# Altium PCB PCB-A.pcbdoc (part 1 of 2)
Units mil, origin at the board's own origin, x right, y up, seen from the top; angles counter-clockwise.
Board outline 4955 x 3850 mil, 4 copper layers (Top Layer, Inner1, Inner2, Bottom Layer); 128 components, 159 nets, 685 pads, 359 vias.
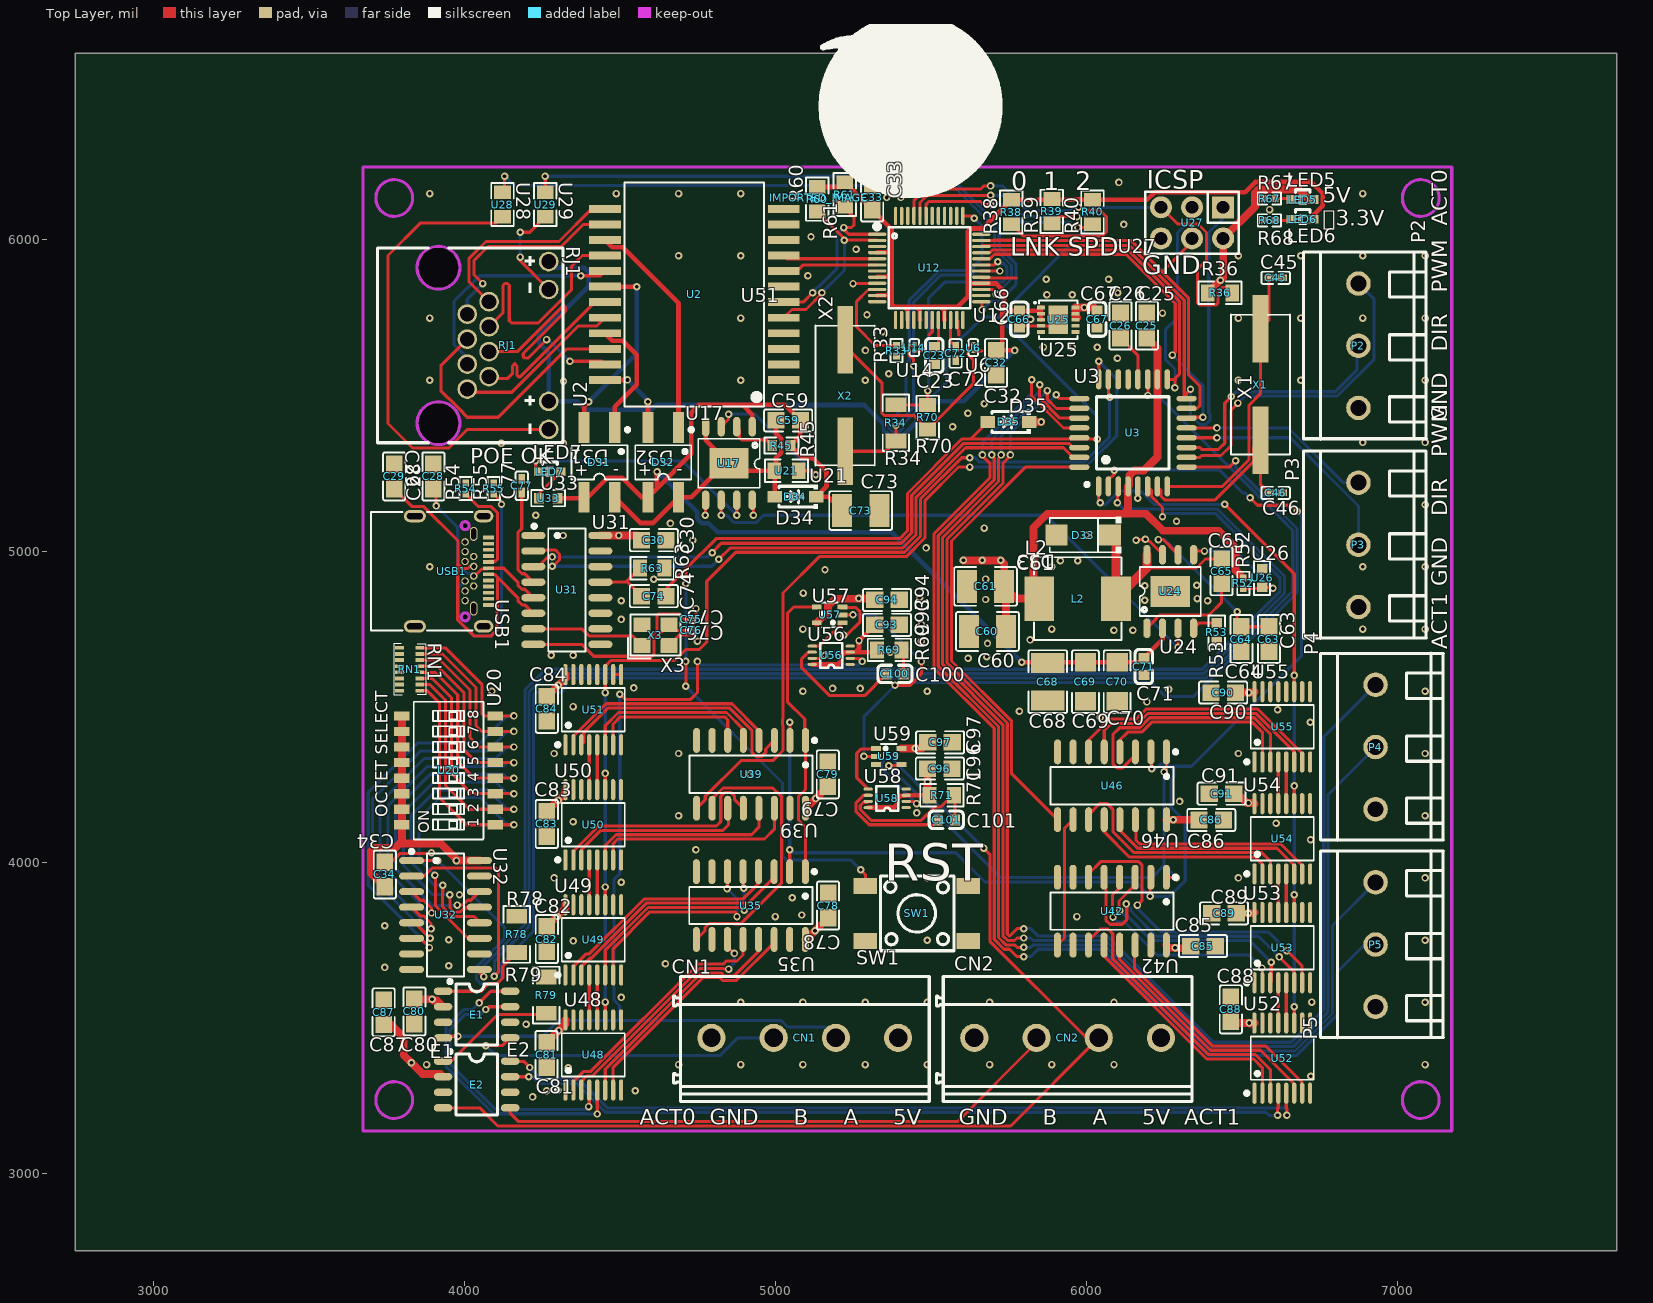
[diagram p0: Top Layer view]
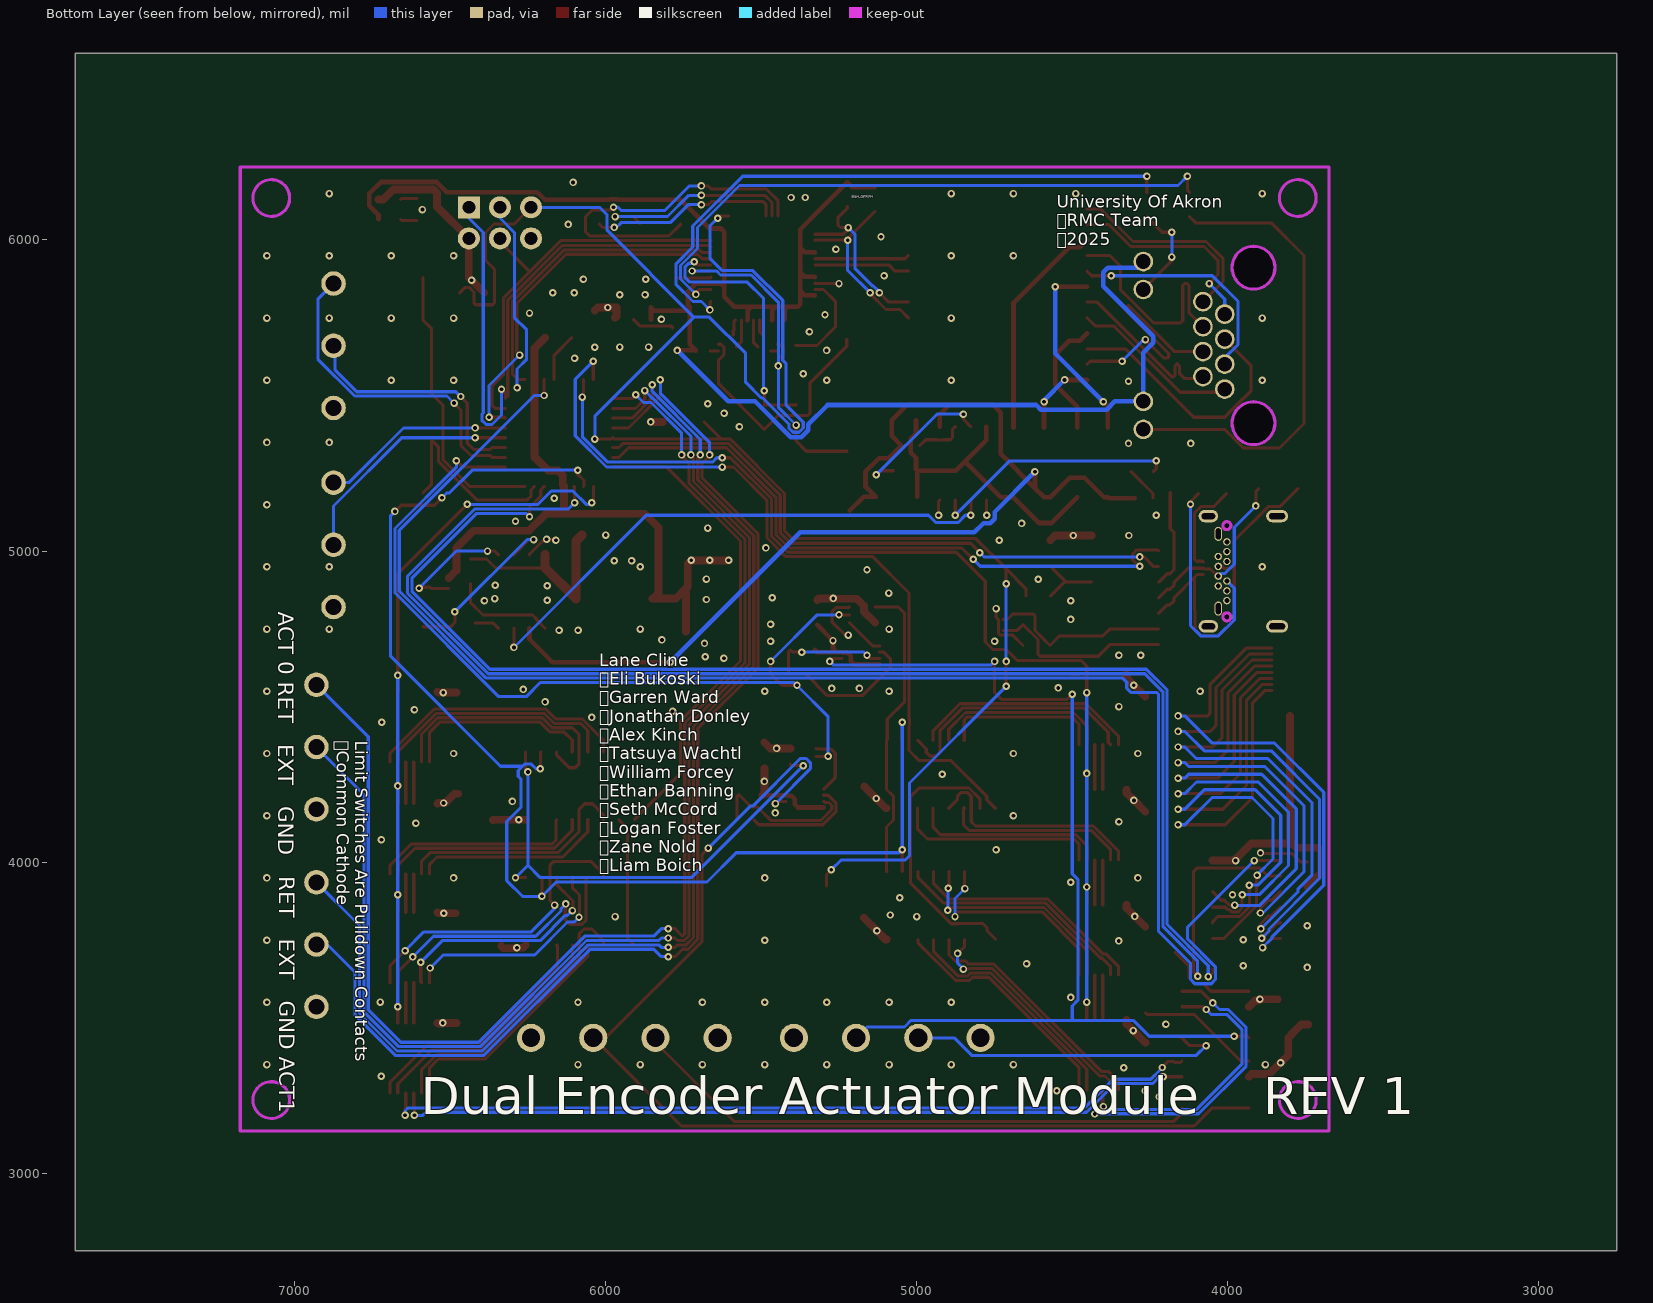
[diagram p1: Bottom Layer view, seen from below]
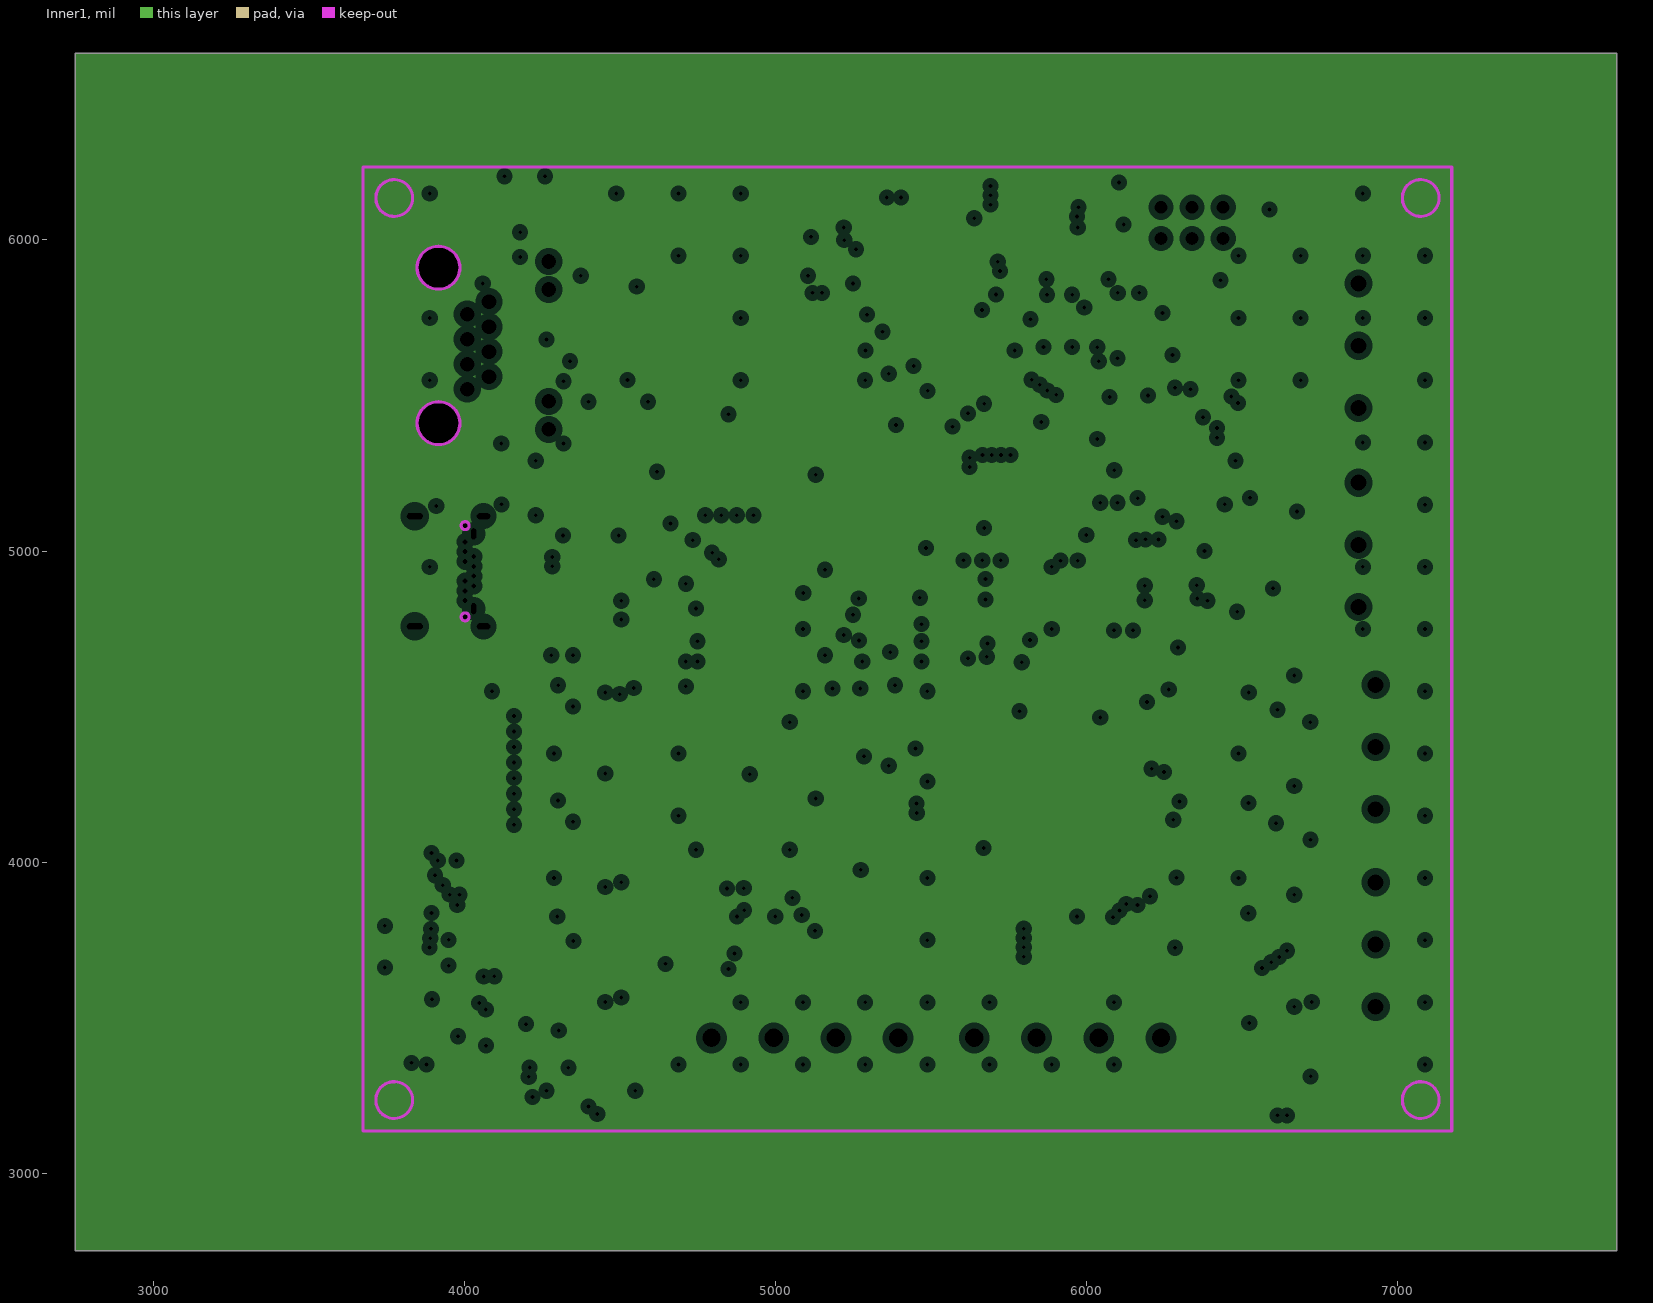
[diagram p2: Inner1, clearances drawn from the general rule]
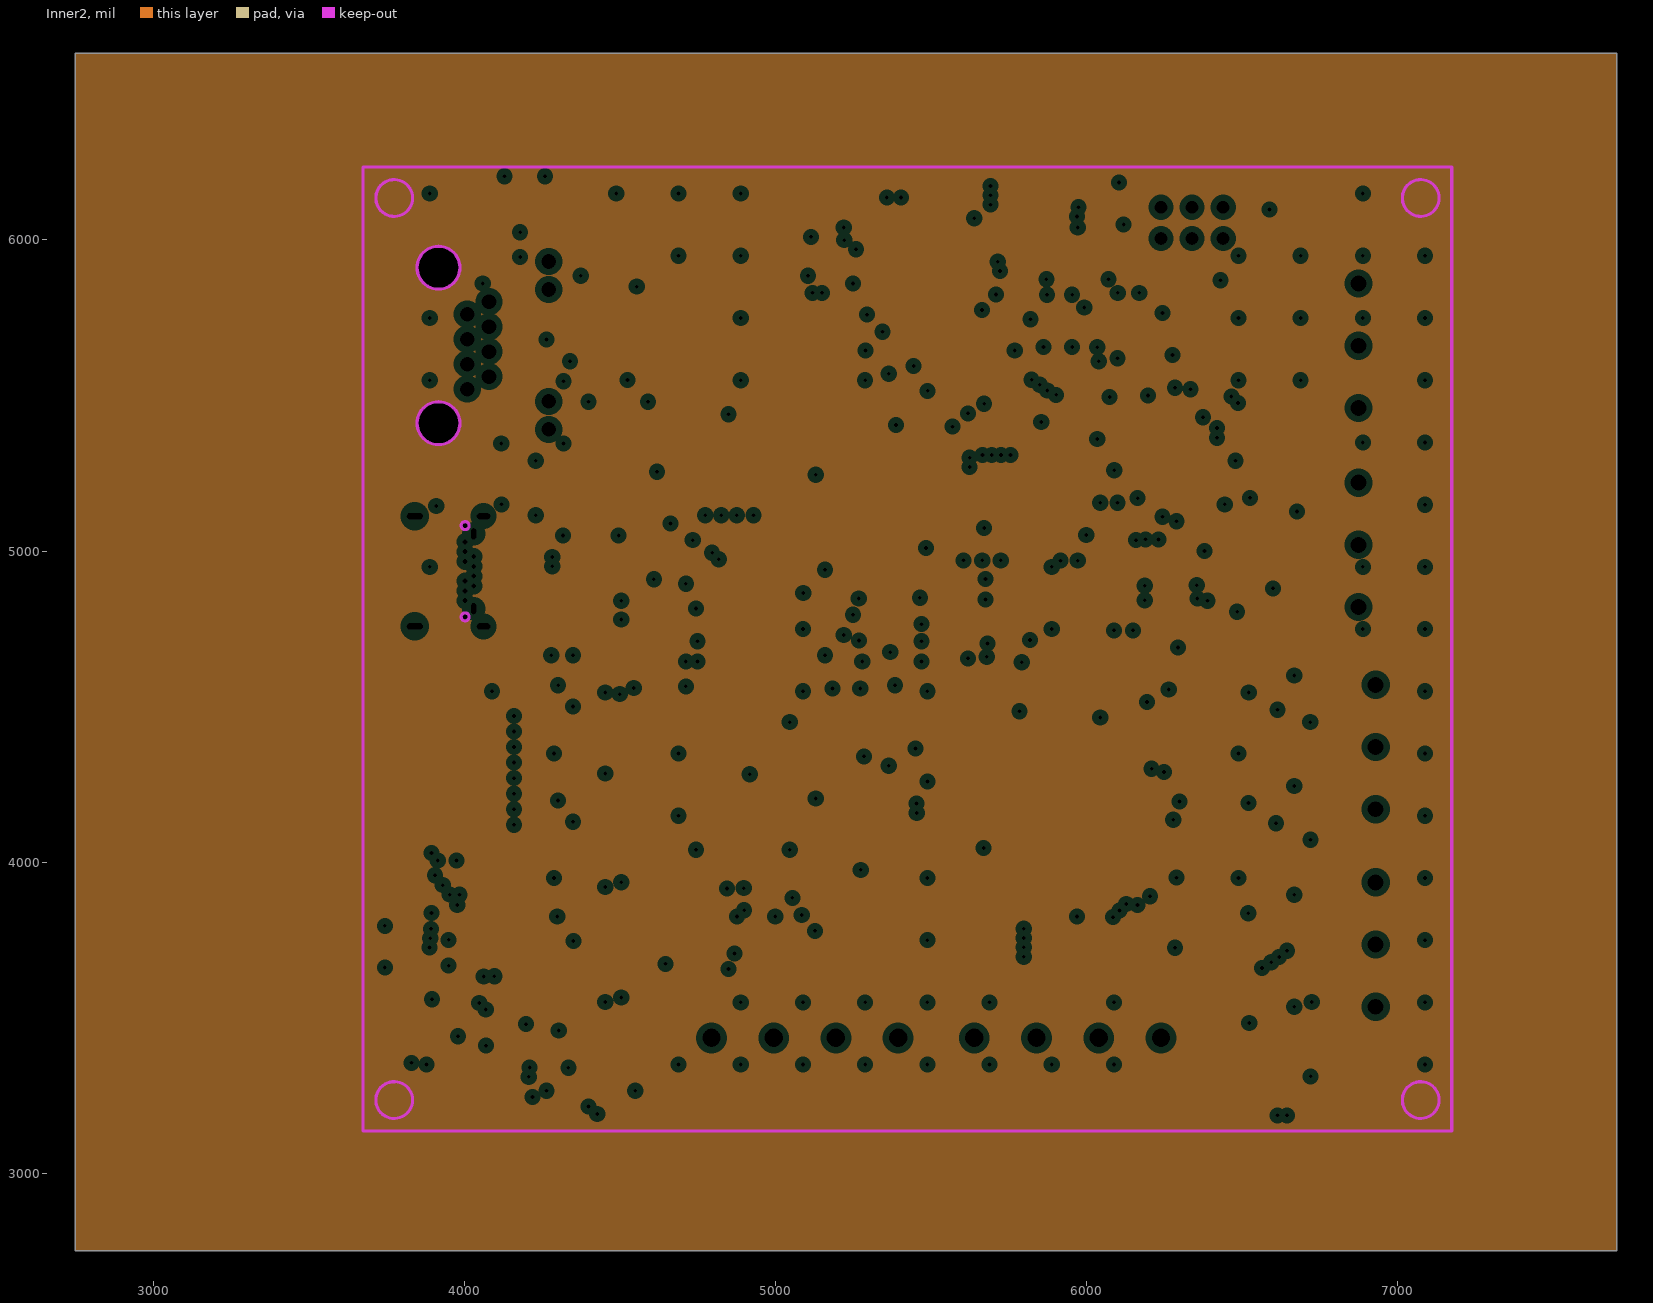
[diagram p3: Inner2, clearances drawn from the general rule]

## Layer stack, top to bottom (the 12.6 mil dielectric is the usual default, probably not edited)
Top Layer: signal copper (thickness not stored)
Dielectric: dielectric 12.6, FR-4, Dk 4.8
Inner1: plane copper (thickness not stored)
Dielectric: dielectric 12.6, FR-4, Dk 4.8
Inner2: plane copper (thickness not stored)
Dielectric: dielectric 12.6, FR-4, Dk 4.8
Bottom Layer: signal copper (thickness not stored)

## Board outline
7705,2750 2750,2750 2750,6600 7705,6600

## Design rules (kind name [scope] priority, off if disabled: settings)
BoardOutlineClearance copperThickness1oz [All] p0: genericclearance=10 ignorepadtopadclearanceinfootprint=FALSE except(0: Arc-SplitContinuation Track-SplitContinuation SMDPad-SplitContinuation THPad-SplitContinuation Via-SplitContinuation Fill-SplitContinuation Poly-SplitContinuation Region-SplitContinuation Text-SplitContinuation; 6: Track-CutoutEdge SMDPad-CutoutEdge THPad-CutoutEdge Via-CutoutEdge Region-CutoutEdge; 11.8: Track-OutlineEdge SMDPad-OutlineEdge THPad-OutlineEdge Via-OutlineEdge Fill-OutlineEdge Region-OutlineEdge Poly-OutlineEdge Text-OutlineEdge Fill-CutoutEdge)
BoardOutlineClearance copperThickness2oz [All] p0: genericclearance=10 ignorepadtopadclearanceinfootprint=FALSE except(0: Arc-SplitContinuation Track-SplitContinuation SMDPad-SplitContinuation THPad-SplitContinuation Via-SplitContinuation Fill-SplitContinuation Poly-SplitContinuation Region-SplitContinuation Text-SplitContinuation; 6: Track-CutoutEdge SMDPad-CutoutEdge THPad-CutoutEdge Via-CutoutEdge Region-CutoutEdge; 11.8: Track-OutlineEdge SMDPad-OutlineEdge THPad-OutlineEdge Via-OutlineEdge Fill-OutlineEdge Region-OutlineEdge Poly-OutlineEdge Text-OutlineEdge Fill-CutoutEdge)
Clearance copperThickness1oz [(InNet('D8') OR InNet('A0') OR InNet('A1') OR InNet('A2') OR InNet('A3') OR InNet('A4') OR InNet('A5') OR InNet('A6') OR InNet('A7') OR InNet('D9') OR InNet('W5500INT') OR InNet('+5V') OR InNet('ETH1A') OR InNet('ETH1B') OR InNet('ETH2A') OR InNet('ETH2B') OR InNet('ETH3A') OR InNet('ETH3B') OR InNet('ETH4A') OR InNet('ETH4B') OR InNet('+33V') OR InNet('RST') OR InNet('DP1') OR InNet('DN1') OR InNet('MISO') OR InNet('SCLK') OR InNet('MOSI') OR InNet('IP5') OR InNet('IP6') OR InNet('IP3') OR InNet('IP4') OR InNet('IP0') OR InNet('IP2') OR InNet('IP1') OR InNet('IP7') OR InNet('D1') OR InNet('D0') OR InNet('W5500CS') OR InNet('OCTR') OR InNet('OCTCLK') OR InNet('AGND') OR InNet('LINKLED') OR InNet('RJ4B') OR InNet('RJ4A') OR InNet('RJ3B') OR InNet('RJ1B') OR InNet('RJ1A') OR InNet('RJ3A') OR InNet('RJ2B') OR InNet('RJ2A') OR InNet('XTAL2') OR InNet('XTAL1') OR InNet('POE+') OR InNet('POE-') OR InNet('CDB') OR InNet('$7N5366') OR InNet('$12N45694') OR InNet('$7N5367') OR InNet('$6N13268') OR InNet('$12N45692') OR InNet('$12N45698') OR InNet('$12N45693') OR InNet('$12N45721') OR InNet('$12N45670') OR InNet('$12N45671') OR InNet('$12N45683') OR InNet('$7N5372') OR InNet('$7N5371') OR InNet('$7N5381') OR InNet('$7N5382') OR InNet('$7N5383') OR InNet('$12N45677') OR InNet('$7N5378') OR InNet('$12N45691') OR InNet('$12N45682') OR InNet('$12N45681') OR InNet('$7N5370') OR InNet('ACTLED') OR InNet('$12N45711') OR InNet('$12N45676') OR InNet('$6N13271') OR InNet('$6N13316') OR InNet('$6N13331') OR InNet('$6N13333') OR InNet('$6N13334') OR InNet('$6N13298') OR InNet('$5N10232') OR InNet('$14N15270') OR InNet('$12N45719') OR InNet('$12N45720') OR InNet('$12N45712') OR InNet('ACT0D1') OR InNet('ACT0D0') OR InNet('$5N10278') OR InNet('$5N10284') OR InNet('ACT0D2') OR InNet('ACT0D3') OR InNet('$5N10573') OR InNet('$5N10565') OR InNet('ACT0D4') OR InNet('ACT0D5') OR InNet('ACT0D6') OR InNet('ACT0D7') OR InNet('$5N9655') OR InNet('ACT0D8') OR InNet('ACT0D9') OR InNet('ACT0D10') OR InNet('ACT0D11') OR InNet('$5N11107') OR InNet('$5N11099') OR InNet('ACT0D12') OR InNet('ACT0D13') OR InNet('ACT0D14') OR InNet('ACT0D15') OR InNet('ACT1D1') OR InNet('ACT1D0') OR InNet('$14N15281') OR InNet('$14N15285') OR InNet('$14N15320') OR InNet('$14N15314') OR InNet('ACT1D4') OR InNet('ACT1D5') OR InNet('ACT1D6') OR InNet('ACT1D7') OR InNet('ACT1D3') OR InNet('ACT1D2') OR InNet('$14N15222') OR InNet('$14N15352') OR InNet('$14N15358') OR InNet('ACT1D8') OR InNet('ACT1D9') OR InNet('ACT1D10') OR InNet('ACT1D11') OR InNet('$14N15396') OR InNet('$14N15390') OR InNet('ACT1D12') OR InNet('ACT1D13') OR InNet('ACT1D14') OR InNet('ACT1D15') OR InNet('$5N14307') OR InNet('$5N14282') OR InNet('ACTCLK') OR InNet('ACTLD') OR InNet('ACT1CLR') OR InNet('ACT1RD') OR InNet('D6') OR InNet('D7') OR InNet('ACT0A') OR InNet('$5N17842') OR InNet('$5N17521') OR InNet('$5N17525') OR InNet('$5N17822') OR InNet('ACT1A') OR InNet('$14N18897') OR InNet('$14N18888') OR InNet('$14N18889') OR InNet('$14N18895') OR InNet('$5N20452') OR InNet('$14N20057'))] p1: gap=7 ignorepadtopadclearanceinfootprint=FALSE except(4: Track-Track; 6: Track-SMDPad SMDPad-SMDPad Track-THPad SMDPad-THPad THPad-THPad Track-Via SMDPad-Via THPad-Via Via-Via SMDPad-Fill THPad-Fill Via-Fill Fill-Fill Track-Region SMDPad-Region THPad-Region Via-Region Region-Region Track-Poly SMDPad-Poly THPad-Poly Via-Poly Fill-Poly Region-Poly Poly-Poly Track-Text SMDPad-Text THPad-Text Via-Text Fill-Text Region-Text Poly-Text Text-Text; 6.9: Track-Hole SMDPad-Hole THPad-Hole Via-Hole Fill-Hole Region-Hole Poly-Hole Text-Hole Sheet-Hole; 11.8: Track-Fill Fill-Region Track-Sheet SMDPad-Sheet THPad-Sheet Via-Sheet Fill-Sheet Region-Sheet Poly-Sheet Text-Sheet)
Clearance copperThickness2oz [All] p1: gap=7 ignorepadtopadclearanceinfootprint=FALSE except(6: Track-SMDPad SMDPad-SMDPad Track-THPad SMDPad-THPad THPad-THPad Track-Via SMDPad-Via THPad-Via Via-Via SMDPad-Fill THPad-Fill Via-Fill Fill-Fill Track-Region SMDPad-Region THPad-Region Via-Region Region-Region Track-Poly SMDPad-Poly THPad-Poly Via-Poly Fill-Poly Region-Poly Poly-Poly Track-Text SMDPad-Text THPad-Text Via-Text Fill-Text Region-Text Poly-Text Text-Text; 6.9: Track-Hole SMDPad-Hole THPad-Hole Via-Hole Fill-Hole Region-Hole Poly-Hole Text-Hole Sheet-Hole; 8: Track-Track; 11.8: Track-Fill Fill-Region Track-Sheet SMDPad-Sheet THPad-Sheet Via-Sheet Fill-Sheet Region-Sheet Poly-Sheet Text-Sheet)
DiffPairsRouting differentialPair [All] p1: maxuncoupledlength=10 minlimit=6 maxlimit=6 mostfreqgap=6 toplayer_minwidth=5 toplayer_prefwidth=10 toplayer_maxwidth=100 bottomlayer_minwidth=5 bottomlayer_prefwidth=10 bottomlayer_maxwidth=100
DiffPairsRouting differentialPair1 [All] p1: maxuncoupledlength=10 minlimit=6 maxlimit=6 mostfreqgap=6 toplayer_minwidth=5 toplayer_prefwidth=10 toplayer_maxwidth=100 bottomlayer_minwidth=5 bottomlayer_prefwidth=10 bottomlayer_maxwidth=100
PasteMaskExpansion pasteMaskExpansion [All] p1: expansion=0
PlaneConnect innerPlane [All] p1: planeconnectstyle=Relief reliefexpansion=20 reliefentries=4 reliefconductorwidth=10 reliefairgap=10
PolygonConnect copperRegion [All] p1: connectstyle=Relief reliefentries=4 reliefconductorwidth=10 polygonreliefangle="90 Angle" airgapwidth=10
RoutingVias viaSize [All] p1: viastyle="Through Hole" holewidth=12 minholewidth=11.8 maxholewidth=248 width=24 minwidth=19.7 maxwidth=393.7
SolderMaskExpansion solderMaskExpansion [All] p1: useseparateexpansions=TRUE expansion=2 expansionbottom=2
Width copperThickness1oz [All] p1: maxlimit=100 minlimit=5 preferedwidth=10
Width copperThickness2oz [All] p1: maxlimit=100 minlimit=8 preferedwidth=10
Width powa [All] p1: maxlimit=50 minlimit=10 preferedwidth=25
Width 3v [All] p1: maxlimit=100 minlimit=10 preferedwidth=15

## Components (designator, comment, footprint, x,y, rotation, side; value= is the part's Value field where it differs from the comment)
C23 "CL10A475KQ8NNNC" C0603 5511.34,5628.82 r90 top
C25 "0805B104K500NT" C0805 6195,5725 r90 top
C26 "0805B104K500NT" C0805 6110,5725 r270 top
C28 "CL21C470JBANNNC" C0805 3901.03,5240 r270 top
C29 "CL21C470JBANNNC" C0805 3775,5240 r270 top
C30 "0805B104K500NT" C0805 4609.79,5035 r0 top
C32 "0805B104K500NT" C0805 5710,5605 r270 top
C33 "0805B104K500NT" C0805 5311.55,6136.59 r90 top
C34 "0805B104K500NT" C0805 3744.79,3960.35 r270 top
C45 "CC0402JRNPO9BN120" C0402 6608.74,5878.41 r0 top
C46 "CC0402JRNPO9BN120" C0402 6608.74,5186.99 r180 top
C59 "0805B104K500NT" C0805 5041.57,5420 r180 top
C60 "CS3225X7R476K160NRL" C1210 5682.35,4741.37 r0 top
C61 "CS3225X7R476K160NRL" C1210 5676.27,4886.37 r0 top
C63 "0805F403M500NT" C0805 6587.35,4717.13 r90 top
C64 "0805F403M500NT" C0805 6498.57,4717.13 r90 top
C65 "0805B104K500NT" C0805 6435,4935 r270 top
C66 "CL10A225KO8NNNC" C0603 5785,5745.33 r90 top
C67 "CL10A225KO8NNNC" C0603 6035,5745.33 r90 top
C68 "FS32X106K101EGG" C1210 5876.04,4580.01 r90 top
C69 "CC1206KKX7R0BB225" C1206 5997.24,4580 r90 top
C70 "CC1206KKX7R0BB225" C1206 6099.31,4580 r90 top
C71 "CC0603KRX7R0BB104" C0603 6185.08,4628.63 r90 top
C72 "CC0402KRX7R9BB103" C0402 5579.8,5635.11 r90 top
C73 "FS32X106K101EGG" C1210 5274.74,5130.26 r180 top
C74 "0805B104K500NT" C0805 4609.79,4855 r180 top
C75 "GRM0225C1E220JA02L" C01005 4730,4780 r180 top
C76 "GRM0225C1E220JA02L" C01005 4730,4745 r180 top
C77 "CC0402JRNPO9BN120" C0402 4185,5209.89 r270 top
C78 "0805B104K500NT" C0805 5170,3860.37 r90 top
C79 "0805B104K500NT" C0805 5168.89,4282.28 r270 top
C80 "0805B104K500NT" C0805 3840,3520 r90 top
C81 "0805B104K500NT" C0805 4265,3380 r270 top
C82 "0805B104K500NT" C0805 4265.66,3752.53 r270 top
C83 "0805B104K500NT" C0805 4265.66,4122.73 r270 top
C84 "0805B104K500NT" C0805 4265.66,4492.93 r270 top
C85 "0805B104K500NT" C0805 6375,3730 r0 top
C86 "0805B104K500NT" C0805 6401.81,4135.37 r180 top
C87 "0805B104K500NT" C0805 3741.36,3517.27 r270 top
C88 "0805B104K500NT" C0805 6464.74,3526.65 r90 top
C89 "0805B104K500NT" C0805 6443.03,3835.37 r180 top
C90 "0805B104K500NT" C0805 6440,4545 r180 top
C91 "0805B104K500NT" C0805 6435,4220 r180 top
C93 "0805B104K500NT" C0805 5359.28,4762.74 r0 top
C94 "0805B104K500NT" C0805 5359.58,4842.74 r180 top
C96 "0805B104K500NT" C0805 5529.19,4300.66 r0 top
C97 "0805B104K500NT" C0805 5530,4385 r180 top
C100 "CC0603JRNPO9BN270" C0603 5385,4605 r0 top
C101 "CC0603JRNPO9BN270" C0603 5550,4135.8 r0 top
CN1 "DB128V-5.08-4P-GN-S" CONN-TH_4P-P5.08_DIBO_DB128V-5.08 5095,3435 r0 top
CN2 "DB128V-5.08-4P-GN-S" CONN-TH_4P-P5.08_DIBO_DB128V-5.08 5940,3435 r0 top
D31 "MB110S_C382811" MBS_L4.7-W4.0-P2.50-LS7.0-BL 4435,5285 r180 top
D32 "MB110S_C382811" MBS_L4.7-W4.0-P2.50-LS7.0-BL 4640,5285 r180 top
D33 "SS36_C727061" SMA_L4.4-W2.6-LS5.0-RD 5990,5051.37 r180 top
D34 "LMSZ5264BT1G" SOD-123_L2.7-W1.6-LS3.7-RD-1 5065,5175 r180 top
D35 "LMSZ5264BT1G" SOD-123_L2.7-W1.6-LS3.7-RD-1 5750,5415 r180 top
E1 "LS7183N-S" SOIC-8_L5.0-W4.0-P1.27-LS6.0-TL 4040,3510 r0 top
E2 "LS7183N-S" SOIC-8_L5.0-W4.0-P1.27-LS6.0-TL 4040,3285 r0 top
IMPORTED_IMAGE "IMPORTED_IMAGE" IMPORTED_IMAGE 5140,6135 r0 top
L2 "FXL0630-8R2-M" IND-SMD_L7.0-W6.6_FXL0630 5972.3,4847.13 r0 top
LED5 "TJ-S1706SW6TGLC7K-A5" LED-SMD_L1.7-W0.6-RD_GREEN 6695.14,6130.02 r0 top
LED6 "TJ-S1706SW6TGLC7K-A5" LED-SMD_L1.7-W0.6-RD_GREEN 6695.14,6066.15 r0 top
LED7 "TJ-S1706SW6TGLC7K-A5" LED-SMD_L1.7-W0.6-RD_GREEN 4275,5255 r0 top
P2 "WJ500V-5.08-3P" CONN-TH_3P-P5.00_WJ500V-5.08-3P 6875,5660 r90 top
P3 "WJ500V-5.08-3P" CONN-TH_3P-P5.00_WJ500V-5.08-3P 6875,5020 r90 top
P4 "WJ500V-5.08-3P" CONN-TH_3P-P5.00_WJ500V-5.08-3P 6930,4370 r90 top
P5 "WJ500V-5.08-3P" CONN-TH_3P-P5.00_WJ500V-5.08-3P 6930,3735 r90 top
R33 "0402WGF1242TCE" R0402 5390,5643.95 r90 top
R34 "1206W4F1004T5E" R1206 5388.04,5412.26 r90 top
R36 "0805W8F1002T5E" R0805 6430,5830 r0 top
R38 "0805W8F0000T5E_C17477" R0805 5759.25,6089.88 r90 top
R39 "0805W8F0000T5E_C17477" R0805 5889.25,6091.98 r90 top
R40 "0805W8F0000T5E_C17477" R0805 6020,6090 r90 top
R45 "0603WAF2492T5E" R0603 5019.98,5339.25 r0 top
R52 "RC0402FR-07100KL" R0402 6504.78,4896.05 r90 top
R53 "0603WAF4992T5E" R0603 6419.36,4738.72 r90 top
R54 "0402WGF5101TCE" R0402 4005,5201.05 r90 top
R55 "0402WGF5101TCE" R0402 4095,5201.05 r90 top
R60 "0805W8F499JT5E" R0805 5134.87,6131.12 r90 top
R61 "0805W8F499JT5E" R0805 5223.47,6146.12 r90 top
R63 "0805W8F1001T5E" R0805 4604.33,4945.18 r0 top
R67 "RC0402FR-071K78L" R0402 6589.27,6133.17 r0 top
R68 "RC0402FR-07845RL" R0402 6589.27,6063 r0 top
R69 "0805W8F1002T5E" R0805 5366.9,4682.11 r0 top
R70 "0805W8F0000T5E_C17477" R0805 5490,5430 r90 top
R71 "0805W8F1002T5E" R0805 5535.38,4215.02 r0 top
R78 "1206W4F1004T5E" R1206 4168.89,3767.57 r270 top
R79 "1206W4F1004T5E" R1206 4263.72,3572.57 r270 top
RJ1 "HC-RJ45-5JA-1-5" RJ45-TH_HC-RJ45-5JA-1-5 4140.86,5660.98 r270 top
RN1 "EXB2HV103JV" RES-ARRAY-SMD_16P-L3.8-W1.6-P0.50-BL 3825,4620 r270 top
SW1 "PTS645SK50SMTR92LFS" KEY-SMD_4P-L6.0-W6.0-P4.50-LS9.0 5455,3835 r180 top
U2 "G24102CE-Z" SMD-24_L18.2-W12.2-P1.27_G24102CE-Z 4740,5825 r90 top
U3 "ATMEGA328PB-AU" TQFP-32_L7.0-W7.0-P0.80-LS9.0-BL 6150,5380 r0 top
U6 "GJM0335C1E180GB01D" C0201 5636.93,5654.07 r90 top
U12 "W5500" LQFP-48_L7.0-W7.0-P0.50-LS9.0-BL 5495,5910 r270 top
U14 "GJM0335C1E180GB01D" C0201 5447.13,5654.07 r90 top
U17 "TPS2378DDAR" SO-8_L4.9-W3.9-P1.27-LS6.0-BL-EP 4851.2,5281.73 r180 top
U20 "DV7SA-08F-01" SW-SMD_DV7SA-08F-01 3950,4295 r90 top
U21 "CR0805F863R4G" R0805 5036.11,5257.97 r0 top
U24 "LMR16030SDDAR" SO-8_L4.9-W3.9-P1.27-LS6.0-BL-EP 6270,4870 r0 top
U25 "NCP3335AMN330R2G" DFN-10_L3.0-W3.0-P0.50-BL-EP-1 5910,5743.56 r270 top
U26 "FRC0603F1782TS" R0603 6565,4913.41 r270 top
U27 "ZX-PZ2.54-2-3PZZ" HDR-TH_6P-P2.54-V-M-R2-C3-S2.54-1 6340,6055 r180 top
U28 "CR0805F863R4G" R0805 4123.18,6113.94 r270 top
U29 "CR0805F863R4G" R0805 4260.75,6113.94 r270 top
U31 "CH340G" SOIC-16_L9.9-W3.9-P1.27-LS6.0-BL 4330,4875 r270 top
U32 "SN74HC165DTR(XBLW)" SOP-16_L9.9-W3.9-P1.27-LS6.0-BL 3940,3830 r270 top
U33 "FRC0603F2672TS" R0603 4270,5170 r180 top
U35 "SN74HC165DTR(XBLW)" SOP-16_L9.9-W3.9-P1.27-LS6.0-BL 4921.58,3860.37 r180 top
U39 "SN74HC165DTR(XBLW)" SOP-16_L9.9-W3.9-P1.27-LS6.0-BL 4922.31,4282.28 r180 top
U42 "SN74HC165DTR(XBLW)" SOP-16_L9.9-W3.9-P1.27-LS6.0-BL 6082.31,3842.28 r180 top
U46 "SN74HC165DTR(XBLW)" SOP-16_L9.9-W3.9-P1.27-LS6.0-BL 6082.68,4245.37 r180 top
U48 "SN74HC193PWR" TSSOP-16_L5.0-W4.4-P0.65-LS6.4-BL 4415,3380 r0 top
U49 "SN74HC193PWR" TSSOP-16_L5.0-W4.4-P0.65-LS6.4-BL 4415,3750 r0 top
U50 "SN74HC193PWR" TSSOP-16_L5.0-W4.4-P0.65-LS6.4-BL 4415,4120 r0 top
U51 "SN74HC193PWR" TSSOP-16_L5.0-W4.4-P0.65-LS6.4-BL 4415,4490 r0 top
U52 "SN74HC193PWR" TSSOP-16_L5.0-W4.4-P0.65-LS6.4-BL 6630,3370 r0 top
U53 "SN74HC193PWR" TSSOP-16_L5.0-W4.4-P0.65-LS6.4-BL 6630,3725 r0 top
U54 "SN74HC193PWR" TSSOP-16_L5.0-W4.4-P0.65-LS6.4-BL 6630,4075 r0 top
U55 "SN74HC193PWR" TSSOP-16_L5.0-W4.4-P0.65-LS6.4-BL 6630,4435 r0 top
U56 "74LVC1G123DC,125" VSSOP-8_L2.4-W2.1-P0.50-LS3.2-BR 5180,4665 r0 top
U57 "74LVC1G32GW,125" SOT-353_L2.2-W1.4-P0.65-LS2.4-BR 5175,4795 r0 top
U58 "74LVC1G123DC,125" VSSOP-8_L2.4-W2.1-P0.50-LS3.2-BR 5360,4205 r0 top
U59 "74LVC1G32GW,125" SOT-353_L2.2-W1.4-P0.65-LS2.4-BR 5365,4340 r180 top
USB1 "HC-TYPE-C-24P-DS10.0-CH2.75S-5A-04" USB-TYPE-C-SMD_HC-TYPE-C-24P-DS10.0-CH2.75S-5A-04 3960,4935 r270 top
X1 "X49SM16MSD2SC" HC-49S_L11.4-W4.8 6559.75,5535 r90 top
X2 "X49SM25MSD2SC" HC-49S_L11.4-W4.8 5225,5500 r90 top
X3 "X322512MOB4SI" CRYSTAL-SMD_4P-L3.2-W2.5-BL 4615,4730 r0 top

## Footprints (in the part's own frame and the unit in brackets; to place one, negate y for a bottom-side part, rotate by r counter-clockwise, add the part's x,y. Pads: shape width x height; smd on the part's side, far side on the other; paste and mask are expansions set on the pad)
C0201 [mil]
  rect 14.51x12.76 smd: 1(-10.8,0) 2(10.8,0)
  silkscreen extent -27,-15 27,15
C0402 [mm]
  rect 0.79x0.54 smd: 1(-0.545,0) 2(0.545,0)
  silkscreen extent -1.17,-0.5 1.17,0.5
C0603 [mm]
  rect 0.8x0.9 smd: 1(-0.7,0) 2(0.7,0)
  silkscreen extent -1.39,-0.71 1.39,0.71
C0805 [mm]
  rect 1.41x1.35 smd: 1(-1,0) 2(1,0)
  silkscreen extent -1.96,-0.9 1.96,0.9
C01005 [mm]
  rect 0.21x0.22 smd: 1(-0.195,0) 2(0.195,0)
  silkscreen extent -0.46,-0.27 0.46,0.27
C1206 [mm]
  rect 1.485x1.728 smd: 1(-1.593,0) 2(1.593,0)
  silkscreen extent -2.56,-1.09 2.56,1.09
C1210 [mm]
  rect 1.635x2.7 smd: 1(-1.517,0) 2(1.517,0)
  silkscreen extent -2.56,-1.58 2.56,1.58
CONN-TH_3P-P5.00_WJ500V-5.08-3P [mm]
  round 2 hole 1.3: 1(-5.08,0) 2(0,0) 3(5.08,0)
  silkscreen extent -7.64,-5.53 7.66,4.5
CONN-TH_4P-P5.08_DIBO_DB128V-5.08 [mm]
  round 2.3 hole 1.5: 1(-7.62,0) 2(-2.54,0) 3(2.54,0) 4(7.62,0)
  silkscreen extent -10.72,-5.2 10.16,5
CRYSTAL-SMD_4P-L3.2-W2.5-BL [mm]
  rect 1.4x1.2 smd: 1(-1.1,-0.85) 2(1.1,-0.85) 3(1.1,0.85) 4(-1.1,0.85)
  silkscreen extent -2.26,-1.91 2.03,1.68
DFN-10_L3.0-W3.0-P0.50-BL-EP-1 [mm]
  rect 0.29x0.65 smd: 1(-1,-1.411) 2(-0.5,-1.411) 3(0,-1.411) 4(0.5,-1.411) 5(1,-1.411) 6(1,1.411) 7(0.5,1.411) 8(0,1.411) 9(-0.5,1.411) 10(-1,1.411)
  rect 2.35x1.58 smd: 11(0,0)
  silkscreen extent -1.58,-1.98 1.58,1.58
HC-49S_L11.4-W4.8 [mm]
  rect 5.5x1.3 smd: 1(-4.553,0) 2(4.553,0)
  silkscreen extent -5.71,-2.41 5.71,2.41
HDR-TH_6P-P2.54-V-M-R2-C3-S2.54-1 [mm]
  rect 1.8x1.8 hole 1.05: 1(-2.54,-1.27)
  round 1.8 hole 1.05: 2(-2.54,1.27) 3(0,-1.27) 4(0,1.27) 5(2.54,-1.27) 6(2.54,1.27)
  silkscreen extent -3.81,-2.54 3.81,2.54
IMPORTED_IMAGE [mil]
  silkscreen extent 0,0 591,628
IND-SMD_L7.0-W6.6_FXL0630 [mm]
  rect 2.424x3.62 smd: 1(3.128,0) 2(-3.128,0)
  silkscreen extent -3.58,-3.38 3.58,3.38
KEY-SMD_4P-L6.0-W6.0-P4.50-LS9.0 [mm]
  rect 1.9x1.3 smd: 1(-4.2,2.25) 2(4.2,2.25) 3(-4.2,-2.25) 4(4.2,-2.25)
  silkscreen extent -3.05,-3.05 2.98,3.05
LED-SMD_L1.7-W0.6-RD_GREEN [mm]
  rect 0.8x0.7 smd: 1(-0.9,0) 2(0.9,0)
  silkscreen extent -0.59,-0.32 0.61,0.8
LQFP-48_L7.0-W7.0-P0.50-LS9.0-BL [mm]
  oval 0.27x1.5 smd: 1(-2.75,-4.25) 2(-2.25,-4.25) 3(-1.75,-4.25) 4(-1.25,-4.25) 5(-0.75,-4.25) 6(-0.25,-4.25) 7(0.25,-4.25) 8(0.75,-4.25) 9(1.25,-4.25) 10(1.75,-4.25) 11(2.25,-4.25) 12(2.75,-4.25) 25(2.75,4.25) 26(2.25,4.25) 27(1.75,4.25) 28(1.25,4.25) 29(0.75,4.25) 30(0.25,4.25) 31(-0.25,4.25) 32(-0.75,4.25) 33(-1.25,4.25) 34(-1.75,4.25) 35(-2.25,4.25) 36(-2.75,4.25)
  oval 1.5x0.27 smd: 13(4.25,-2.75) 14(4.25,-2.25) 15(4.25,-1.75) 16(4.25,-1.25) 17(4.25,-0.75) 18(4.25,-0.25) 19(4.25,0.25) 20(4.25,0.75) 21(4.25,1.25) 22(4.25,1.75) 23(4.25,2.25) 24(4.25,2.75) 37(-4.25,2.75) 38(-4.25,2.25) 39(-4.25,1.75) 40(-4.25,1.25) 41(-4.25,0.75) 42(-4.25,0.25) 43(-4.25,-0.25) 44(-4.25,-0.75) 45(-4.25,-1.25) 46(-4.25,-1.75) 47(-4.25,-2.25) 48(-4.25,-2.75)
  silkscreen extent -3.59,-4.46 3.3,3.34
MBS_L4.7-W4.0-P2.50-LS7.0-BL [mm]
  rect 0.91x2.495 smd: 1(-1.25,-2.848) 2(1.25,-2.848) 3(1.25,2.848) 4(-1.25,2.848)
  silkscreen extent -2.44,-2.82 2.29,1.4
R0402 [mm]
  rect 0.566x0.54 smd: 1(-0.433,0) 2(0.433,0)
  silkscreen extent -0.94,-0.5 0.94,0.5
R0603 [mil]
  rect 31.75x34.02 smd: 1(-29.66,0) 2(29.66,0)
  silkscreen extent -55,-26 55,26
R0805 [mm]
  rect 1.133x1.377 smd: 1(-1,0) 2(1,0)
  silkscreen extent -1.76,-0.92 1.76,0.92
R1206 [mil]
  rect 47.54x66.97 smd: 1(-58.22,0) 2(58.22,0)
  silkscreen extent -91,-42 91,42
RES-ARRAY-SMD_16P-L3.8-W1.6-P0.50-BL [mm]
  rect 0.3x0.7 smd: 1(-1.75,-0.833) 2(-1.25,-0.833) 3(-0.75,-0.833) 4(-0.25,-0.833) 5(0.25,-0.833) 6(0.75,-0.833) 7(1.25,-0.833) 8(1.75,-0.833) 9(1.75,0.833) 10(1.25,0.833) 11(0.75,0.833) 12(0.25,0.833) 13(-0.25,0.833) 14(-0.75,0.833) 15(-1.25,0.833) 16(-1.75,0.833)
  silkscreen extent -2.1,-1.3 2.1,1.3
RJ45-TH_HC-RJ45-5JA-1-5 [mm]
  round 1.6 hole 1.2: 1(3.57,-3.325) 2(2.55,-1.545) 3(1.53,-3.325) 4(0.51,-1.545) 5(-0.51,-3.325) 6(-1.53,-1.545) 7(-2.55,-3.325) 8(-3.57,-1.545) 9(-6.85,3.325) 10(-4.57,3.325) 11(4.57,3.325)
  round 1.6 hole 1.2 copper offset 0,0: 12(6.85,3.325)
  Board Outline Layer circle w0.005: c-6.35,-5.675 r1.75
  Board Outline Layer circle w0.005: c6.35,-5.675 r1.75
  Board Outline Layer circle w0.254: c-6.35,-5.675 r1.75
  Board Outline Layer circle w0.254: c6.35,-5.675 r1.75
  Multi-Layer board cut-out: -6.35,-3.925 -7.219,-4.164 -7.853,-4.804 -8.085,-5.675 -7.853,-6.546 -7.219,-7.185 -6.35,-7.425 -6.35,-7.425 -5.481,-7.185 -4.847,-6.546 -4.615,-5.675 -4.847,-4.804 -5.481,-4.164 -6.35,-3.925
  Multi-Layer board cut-out: 6.35,-3.925 5.481,-4.164 4.847,-4.804 4.615,-5.675 4.847,-6.546 5.481,-7.185 6.35,-7.425 6.35,-7.425 7.219,-7.185 7.853,-6.546 8.085,-5.675 7.853,-4.804 7.219,-4.164 6.35,-3.925
  silkscreen extent -7.95,-10.65 7.95,4.5
SMA_L4.4-W2.6-LS5.0-RD [mm]
  rect 1.8x1.7 smd: 1(-2.193,0) 2(2.193,0)
  silkscreen extent -3.11,-1.48 2.73,1.48
SMD-24_L18.2-W12.2-P1.27_G24102CE-Z [mm]
  rect 0.644x2.6 smd: 1(-6.985,-7.3) 2(-5.715,-7.3) 3(-4.445,-7.3) 4(-3.175,-7.3) 5(-1.905,-7.3) 6(-0.635,-7.3) 7(0.635,-7.3) 8(1.905,-7.3) 9(3.175,-7.3) 10(4.445,-7.3) 11(5.715,-7.3) 12(6.985,-7.3) 13(6.985,7.3) 14(5.715,7.3) 15(4.445,7.3) 16(3.175,7.3) 17(1.905,7.3) 18(0.635,7.3) 19(-0.635,7.3) 20(-1.905,7.3) 21(-3.175,7.3) 22(-4.445,7.3) 23(-5.715,7.3) 24(-6.985,7.3)
  silkscreen extent -9.14,-5.7 9.14,5.7
SO-8_L4.9-W3.9-P1.27-LS6.0-BL-EP [mm]
  oval 0.6x1.6 smd: 1(-1.905,-3) 2(-0.635,-3) 3(0.635,-3) 4(1.905,-3) 5(1.905,3) 6(0.635,3) 7(-0.635,3) 8(-1.905,3)
  rect 3.2x2.5 smd: 9(0,0)
  silkscreen extent -2.5,-2 2.5,2
SOD-123_L2.7-W1.6-LS3.7-RD-1 [mm]
  rect 1.2x0.95 smd: 1(-1.7,0) 2(1.7,0)
  silkscreen extent -1.81,-0.98 1.35,0.98
SOIC-8_L5.0-W4.0-P1.27-LS6.0-TL [mm]
  oval 1.52x0.6 smd: 1(-2.74,1.905) 2(-2.74,0.635) 3(-2.74,-0.635) 4(-2.74,-1.905) 5(2.74,-1.905) 6(2.74,-0.635) 7(2.74,0.635) 8(2.74,1.905)
  silkscreen extent -2.33,-2.5 1.7,2.84
SOIC-16_L9.9-W3.9-P1.27-LS6.0-BL [mil]
  oval 23.7x77.6 smd: 1(-175,-107.7) 2(-125,-107.7) 3(-75,-107.7) 4(-25,-107.7) 5(25,-107.7) 6(75,-107.7) 7(125,-107.7) 8(175,-107.7) 9(175,107.7) 10(125,107.7) 11(75,107.7) 12(25,107.7) 13(-25,107.7) 14(-75,107.7) 15(-125,107.7) 16(-175,107.7)
  silkscreen extent -211,-111 198,60
SOP-16_L9.9-W3.9-P1.27-LS6.0-BL [mil]
  oval 22.6x80.24 smd: 1(-175,-109.02) 2(-125,-109.02) 3(-75,-109.02) 4(-25,-109.02) 5(25,-109.02) 6(75,-109.02) 7(125,-109.02) 8(175,-109.02) 9(175,109.02) 10(125,109.02) 11(75,109.02) 12(25,109.02) 13(-25,109.02) 14(-75,109.02) 15(-125,109.02) 16(-175,109.02)
  silkscreen extent -210,-115 198,60
SOT-353_L2.2-W1.4-P0.65-LS2.4-BR [mm]
  rect 0.8x0.4 smd: 1(1.05,-0.65) 2(1.05,0) 3(1.05,0.65) 4(-1.05,0.65) 5(-1.05,-0.65)
  silkscreen extent -0.64,-1.02 0.64,1.02
SW-SMD_DV7SA-08F-01 [mm]
  rect 0.76x1.27 smd: 1(-4.445,-3.81) 2(-3.175,-3.81) 3(-1.905,-3.81) 4(-0.635,-3.81) 5(0.635,-3.81) 6(1.905,-3.81) 7(3.175,-3.81) 8(4.445,-3.81) 9(4.445,3.81) 10(3.175,3.81) 11(1.905,3.81) 12(0.635,3.81) 13(-0.635,3.81) 14(-1.905,3.81) 15(-3.175,3.81) 16(-4.445,3.81)
  silkscreen extent -5.64,-2.85 5.61,2.85
TQFP-32_L7.0-W7.0-P0.80-LS9.0-BL [mm]
  oval 0.45x1.65 smd: 1(-2.8,-4.369) 2(-2,-4.369) 3(-1.2,-4.369) 4(-0.4,-4.369) 5(0.4,-4.369) 6(1.2,-4.369) 7(2,-4.369) 8(2.8,-4.369) 17(2.8,4.369) 18(2,4.369) 19(1.2,4.369) 20(0.4,4.369) 21(-0.4,4.369) 22(-1.2,4.369) 23(-2,4.369) 24(-2.8,4.369)
  oval 1.65x0.45 smd: 9(4.381,-2.8) 10(4.381,-2) 11(4.381,-1.2) 12(4.381,-0.4) 13(4.381,0.4) 14(4.381,1.2) 15(4.381,2) 16(4.381,2.8) 25(-4.381,2.8) 26(-4.381,2) 27(-4.381,1.2) 28(-4.381,0.4) 29(-4.381,-0.4) 30(-4.381,-1.2) 31(-4.381,-2) 32(-4.381,-2.8)
  silkscreen extent -3.91,-4.36 2.94,2.95
TSSOP-16_L5.0-W4.4-P0.65-LS6.4-BL [mil]
  oval 13.5x68.17 smd: 1(-89.57,-112.82) 2(-63.98,-112.82) 3(-38.39,-112.82) 4(-12.79,-112.82) 5(12.8,-112.82) 6(38.39,-112.82) 7(63.98,-112.82) 8(89.57,-112.82) 9(89.57,112.82) 10(63.98,112.82) 11(38.39,112.82) 12(12.8,112.82) 13(-12.79,112.82) 14(-38.39,112.82) 15(-63.98,112.82) 16(-89.57,112.82)
  silkscreen extent -120,-119 101,70
USB-TYPE-C-SMD_HC-TYPE-C-24P-DS10.0-CH2.75S-5A-04 [mm]
  oval 1x1.6 hole 0.5 slot 1.1 at 90 deg: 25(4.5,2.605) 28(-4.5,2.605)
  oval 1x1.8 hole 0.5 slot 1.3 at 90 deg: 26(4.5,-3.005) 27(-4.5,-3.005)
  rect 0.3x0.9 smd: A1(-2.75,3.005) A2(-2.25,3.005) A3(-1.75,3.005) A4(-1.25,3.005) A5(-0.75,3.005) A6(-0.25,3.005) A7(0.25,3.005) A8(0.75,3.005) A9(1.25,3.005) A10(1.75,3.005) A11(2.25,3.005) A12(2.75,3.005)
  oval 1.15x0.6 hole 0.4 slot 0.9 at 0 deg: B1(3.05,1.795)
  round 0.6 hole 0.4: B2(2.4,1.095) B3(1.6,1.095) B4(1.2,1.795) B5(0.8,1.095) B6(0.4,1.795) B7(-0.4,1.795) B9(-1.2,1.795) B10(-1.6,1.095) B11(-2.4,1.095)
  round 0.6 hole 0.4 copper offset 0,0: B8(-0.8,1.095)
  oval 1.15x0.6 hole 0.4 slot 0.9 at 0 deg copper offset 0,0: B12(-3.05,1.795)
  Board Outline Layer circle w0.005: c-3.725,1.095 r0.325
  Board Outline Layer circle w0.005: c3.725,1.095 r0.325
  Board Outline Layer circle w0.254: c-3.725,1.095 r0.325
  Board Outline Layer circle w0.254: c3.725,1.095 r0.325
  Multi-Layer board cut-out: -3.725,1.42 -3.885,1.374 -4.001,1.256 -4.043,1.095 -4.001,0.934 -3.885,0.816 -3.725,0.77 -3.725,0.77 -3.565,0.816 -3.449,0.934 -3.406,1.095 -3.449,1.256 -3.565,1.374 -3.725,1.42
  Multi-Layer board cut-out: 3.725,1.42 3.565,1.374 3.449,1.256 3.406,1.095 3.449,0.934 3.565,0.816 3.725,0.77 3.725,0.77 3.885,0.816 4.001,0.934 4.043,1.095 4.001,1.256 3.885,1.374 3.725,1.42
  silkscreen extent -4.83,-6.6 4.83,1.71
VSSOP-8_L2.4-W2.1-P0.50-LS3.2-BR [mm]
  oval 0.75x0.25 smd: 1(1.55,-0.75) 2(1.55,-0.25) 3(1.55,0.25) 4(1.55,0.75) 5(-1.55,0.75) 6(-1.55,0.25) 7(-1.55,-0.25) 8(-1.55,-0.75)
  silkscreen extent -0.9,-1.02 0.9,1

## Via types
v1: diameter 24, hole 12, Top Layer to Bottom Layer, 345 vias
v2: diameter 24.02, hole 12.01, Top Layer to Bottom Layer, 14 vias

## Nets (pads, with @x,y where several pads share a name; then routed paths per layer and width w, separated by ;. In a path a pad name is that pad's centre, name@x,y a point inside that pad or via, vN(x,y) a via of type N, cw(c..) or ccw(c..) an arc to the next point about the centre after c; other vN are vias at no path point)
$5N9655: U35.9 U39.10 | length 911.7
  Top Layer w10: U35.9@4746.58,3751.35 4774.28,3779.05 4774.28,3789.41 4787.34,3802.47 4867.07,3802.47 4867.54,3802 4889.53,3802 5019.61,3932.08 5019.61,4211.32 4992.54,4238.38 4832.27,4238.38 4797.31,4203.41 U39.10@4797.31,4173.26
$5N10232: CN1.2 E1.5 | length 1049.5
  Top Layer w10: v1(4070,3410) 4122.87,3410 E1.5@4147.87,3435
  Bottom Layer w10: v1(4070,3410) 4101.28,3378.72 4823.72,3378.72 4880,3435 CN1.2@4995,3435
$5N10278: E1.7 U48.4 | length 900.5
  Top Layer w10: v1(4069.44,3526.13) 4078.31,3535 E1.7@4147.87,3535 ; v1(4400,3214) 4402.21,3216.21 U48.4@4402.21,3267.18
  Bottom Layer w10: v1(4069.44,3526.13) 4053.89,3510.57 4003.25,3510.57 3955,3462.33 3955,3350 4100,3205 4395,3205 4400,3210 v1(4400,3214)
$5N10284: E1.8 U48.5 | length 1003
  Top Layer w10: v1(4048.23,3547.34) 4085.89,3585 E1.8@4147.87,3585 ; U48.5@4426.96,3263 4427.8,3262.16 v1(4427.8,3190.17)
  Bottom Layer w10: v1(4048.23,3547.34) 4026.89,3526 3998.88,3526 3941,3468.12 3941,3344.2 4094.2,3191 4395,3191 4395.83,3190.17 v1(4427.8,3190.17)
$5N10565: U48.12 U49.5 | length 144.4
  Top Layer w10: U48.12@4427.8,3492.82 U49.5@4427.8,3637.18
$5N10573: U48.13 U49.4 | length 144.4
  Top Layer w10: U48.13@4402.21,3492.82 U49.4@4402.21,3637.18
$5N11099: U50.12 U51.5 | length 144.4
  Top Layer w10: U50.12@4427.8,4232.82 U51.5@4427.8,4377.18
$5N11107: U50.13 U51.4 | length 144.4
  Top Layer w10: U50.13@4402.21,4232.82 U51.4@4402.21,4377.18
$5N14282: U49.12 U50.5 | length 144.4
  Top Layer w10: U49.12@4427.8,3862.82 U50.5@4427.8,4007.18
$5N14307: U49.13 U50.4 | length 144.4
  Top Layer w10: U49.13@4402.21,3862.82 U50.4@4402.21,4007.18
$5N17521: C100.2 R69.2 U56.7 | length 378.2
  Top Layer w10: U56.7@5118.98,4655.16 5150.16,4655.16 v1(5160,4665) ; v1(5370,4675) 5399.16,4675 R69.2@5406.27,4682.11 5412.56,4675.82 C100.2@5412.56,4605
  Bottom Layer w10: v1(5160,4665) 5170,4675 v1(5370,4675)
$5N17525: C100.1 U56.6 | length 410.2
  Top Layer w10: U56.6@5118.98,4674.84 5118.83,4675 5106.46,4675 5085,4653.54 5085,4625 5175,4535 5287.44,4535 C100.1@5357.44,4605
$5N17822: U56.5 U57.1 | length 128.4
  Top Layer w10: U56.5@5118.98,4694.53 5141.46,4694.53 U57.1@5216.34,4769.41
$5N17842: U35.1 U39.1 U57.4 | length 976.1
  Top Layer w10: U35.1@5096.58,3969.39 5097.31,3970.12 5097.31,4112.91 5075.01,4135.21 5075.01,4211.32 5097.31,4233.62 U39.1@5097.31,4391.3 5095,4393.61 5095,4460 5039,4516 5039,4799 5060,4820 5133.07,4820 U57.4@5133.66,4820.59
$5N20452: E1.1 R78.2 | length 310.1
  Top Layer w10: E1.1@3932.13,3585 4054.37,3585 4079.19,3609.82 4106.62,3609.82 4124,3627.2 4124,3664.46 R78.2@4168.89,3709.35
$6N13268: C26.2 U3.20 | length 156.7
  Top Layer w10: C26.2@6110,5685.63 6165.75,5629.88 U3.20@6165.75,5552
$6N13271: R54.1 USB1.A5 | length 309
  Top Layer w10: R54.1@4005,5184.01 4046.15,5142.85 4087.07,5142.85 4107.03,5122.9 4107.03,4973.75 4100.58,4967.3 4081.08,4967.3 USB1.A5@4078.31,4964.53
$6N13298: C77.2 U31.4 | length 319.7
  Top Layer w10: C77.2@4185,5188.43 4185,5071.96 4172.5,5059.47 4172.5,4940.53 4185.89,4927.15 4195.15,4927.15 U31.4@4222.3,4900
$6N13316: R55.1 USB1.B5 | length 745.2
  Top Layer w10: R55.1@4095,5184.01 4120,5159.01 v1(4120,5150)
  Bottom Layer w10: USB1.B5@4003.11,4903.51 3994.41,4894.82 3993.65,4894.82 3979.32,4880.48 3979.32,4778.49 4030.65,4727.15 4087.07,4727.15 4120,4760.08 v1(4120,5150)
$6N13331: C74.2 R63.1 U31.13 | length 215.2
  Top Layer w10: U31.13@4437.7,4900 4519.78,4900 ; R63.1@4564.96,4945.18 4519.78,4900 ; C74.2@4570.42,4855 4525.42,4900 4519.78,4900
$6N13333: C75.2 U31.7 X3.1 | length 599.3
  Top Layer w10: U31.7@4222.3,4750 4378.44,4750 4401.29,4727.15 4541.08,4727.15 X3.1@4571.69,4696.53 4596.25,4721.09 4596.25,4721.2 4619.75,4744.7 4619.75,4791.64 4626.19,4798.09 4690.43,4798.09 4708.51,4780 C75.2@4722.32,4780
$6N13334: C76.2 U31.8 X3.3 | length 593.1
  Top Layer w10: U31.8@4222.3,4700 4378.44,4700 4416.52,4661.91 4603.81,4661.91 4610.25,4668.36 4610.25,4715.4 X3.3@4658.31,4763.47 4676.77,4745 C76.2@4722.32,4745
$7N5366: R33.2 U12.10 | length 312.7
  Top Layer w10: 5296.71,5837.73 5261.59,5802.62 5261.59,5720 5320.6,5660.99 R33.2@5390,5660.99 ; U12.10@5300.07,5841.1 U12.10@5327.68,5841.1
$7N5367: C23.2 U12.20 | length 91.8
  Top Layer w10: C23.2@5511.34,5656.38 5524.53,5669.57 U12.20@5524.53,5742.68
$7N5370: C72.2 U12.22 | length 92.7
  Top Layer w10: U12.22@5563.9,5742.68 5563.9,5672.48 C72.2@5579.8,5656.57
$7N5371: R34.1 U12.30 U14.2 X2.1 | length 1113.5
  Top Layer w10: X2.1@5225,5320.75 5354.75,5320.75 R34.1@5388.04,5354.04 v1(5388.04,5405) ; v1(5445,5595) 5445,5616.21 5429.75,5631.46 5429.75,5655.08 5436.19,5661.53 5443.78,5661.53 U14.2@5447.13,5664.87 ; U12.30@5662.32,5900.16 5669.07,5900.16 5669.2,5900.29 v1(5722.5,5900.29)
  Bottom Layer w10: v1(5388.04,5405) 5445,5461.96 v1(5445,5595) 5445,5800 5532.53,5887.53 5630.8,5887.53 5643.56,5900.29 v1(5722.5,5900.29)
$7N5372: R34.2 R70.2 U12.31 | length 854.1
  Top Layer w10: R34.2@5388.04,5470.48 5389.15,5469.37 R70.2@5490,5469.37 v1(5490,5515) ; U12.31@5662.32,5919.84 5705.12,5919.84 v1(5715.17,5929.89)
  Bottom Layer w10: v1(5490,5515) 5492.5,5517.5 5492.5,5812.5 5544.53,5864.53 5729.53,5864.53 5745.5,5880.5 5745.5,5912.19 5732.66,5925.03 5720.03,5925.03 v1(5715.17,5929.89)
$7N5378: R70.1 U6.2 X2.2 | length 809.4
  Top Layer w10: X2.2@5225,5679.25 5225,5658.21 5343.56,5539.66 5343.56,5442.15 5350,5435.71 5447.51,5435.71 5447.51,5433.12 R70.1@5490,5390.63 5636.93,5537.56 5636.93,5614.09 5619.55,5631.46 5619.55,5655.08 5629.34,5664.87 U6.2@5636.93,5664.87
$7N5381: R38.1 U12.45 | length 1112.8
  Top Layer w10: U12.45@5445.79,6077.32 5445.79,6125.79 5483.29,6163.29 5660,6163.29 5670.32,6173.61 v2(5692.33,6173.61) ; R38.1@5759.25,6050.51 5797.16,6012.6 6051.44,6012.6 6065,6026.15 6065,6075 6043.91,6096.09 5988.34,6096.09 5979.12,6105.32 v2(5974.9,6105.32)
  Bottom Layer w10: v2(5692.33,6173.61) 5731.39,6173.61 5810,6095 5950,6095 5960.32,6105.32 v2(5974.9,6105.32)
$7N5382: R39.1 U12.44 | length 675.5
  Top Layer w10: U12.44@5465.47,6077.32 5465.47,6120.47 5488.61,6143.61 v2(5692.33,6143.61) ; R39.1@5889.25,6052.61 5911.95,6075.32 v2(5969.9,6075.32)
  Bottom Layer w10: v2(5692.33,6143.61) 5732.81,6143.61 5801.1,6075.32 v2(5969.9,6075.32)
$7N5383: R40.1 U12.43 | length 615.2
  Top Layer w10: U12.43@5485.16,6077.32 5485.16,6115.16 5493.92,6123.92 5660,6123.92 5670.32,6113.61 v2(5692.33,6113.61) ; v2(5972.33,6040.32) 6009.69,6040.32 R40.1@6020,6050.63
  Bottom Layer w10: v2(5692.33,6113.61) 5734.97,6113.61 5792.94,6055.63 5950,6055.63 5965.32,6040.32 v2(5972.33,6040.32)
$12N45670: D31.2 U2.18 | length 625.4
  Top Layer w15: D31.2@4385.78,5397.11 4385.78,5465.78 v1(4400,5480) ; U2.18@4452.6,5850 v1(4555,5850)
  Bottom Layer w15: v1(4400,5480) 4555,5635 v1(4555,5850)
$12N45671: D32.1 U2.15 | length 720.2
  Top Layer w15: U2.15@4452.6,6000 4476.42,5976.18 4509.37,5976.18 4689.22,5796.33 D32.1@4689.22,5397.11
$12N45676: U17.3 U21.2 | length 470.7
  Top Layer w10: U17.3@4826.2,5399.84 4850,5423.64 v1(4850,5440) ; U21.2@5075.48,5257.97 5117.03,5257.97 v1(5130,5245)
  Bottom Layer w10: v1(4850,5440) 4935,5440 v1(5130,5245)
$12N45677: R45.1 U17.2 | length 155
  Top Layer w10: U17.2@4876.2,5399.84 4885,5391.03 4885,5365 4892.07,5357.93 4916.16,5357.93 4916.75,5357.34 4935.64,5357.34 4936.23,5357.93 4971.65,5357.93 R45.1@4990.32,5339.25
$12N45681: RJ1.12 U28.2 | length 1534.2
  Top Layer w10: U28.2@4123.18,6074.57 4103.6,6055 3860,6055 3755,5950 3755,5410 3833.91,5331.09 3950.53,5331.09 4010.74,5391.3 RJ1.12@4271.77,5391.31
$12N45682: RJ1.10 U29.2 | length 323.4
  Top Layer w10: v1(4180,5945) 4180,5932.67 RJ1.10@4271.77,5840.91 ; v1(4180,6025) 4211.18,6025 U29.2@4260.75,6074.57
  Bottom Layer w10: v1(4180,5945) v1(4180,6025)
$12N45683: D32.2 U2.24 | length 252.5
  Top Layer w15: U2.24@4452.6,5550 v1(4525,5550) ; D32.2@4590.78,5397.11 v1(4590.78,5480)
  Bottom Layer w15: v1(4525,5550) 4590.78,5484.22 v1(4590.78,5480)
$12N45691: R53.2 U24.4 | length 81.2
  Top Layer w10: U24.4@6345,4751.89 6361.49,4768.38 R53.2@6419.36,4768.38
$12N45692: C63.2 C64.2 U24.6 | length 576.5
  Top Layer w10: v1(6231.89,5036.84) 6248.21,5036.84 6267.81,5017.24 6267.81,5015.3 U24.6@6295,4988.11 ; v1(6485,4805) 6485,4770.07 C64.2@6498.57,4756.5 C63.2@6587.35,4756.5
  Bottom Layer w10: v1(6231.89,5036.84) 6253.16,5036.84 v1(6485,4805)
$12N45693: C65.1 D33.1 L2.1 U24.8 | length 646.7
  Top Layer w10: 6195,4946.68 6196.07,4945.61 6354.45,4945.61 6383.2,4974.37 C65.1@6435,4974.37
  Top Layer w30: D33.1@6076.32,5051.37 6095.45,5032.24 L2.1@6095.45,4847.13 6195,4946.68 U24.8@6195,4988.11
$12N45694: R52.1 U24.5 U26.2 | length 408.4
  Top Layer w10: U24.5@6345,4988.11 6356.89,5000 v1(6380,5000) ; R52.1@6504.78,4879.01 6560.26,4879.01 U26.2@6565,4883.75 6596.25,4883.75 v1(6600,4880)
  Bottom Layer w10: v1(6380,5000) 6480,5000 v1(6600,4880)
$12N45698: C65.2 U24.1 | length 336.2
  Top Layer w10: U24.1@6195,4751.89 6222.19,4779.08 6222.19,4781.02 6235.55,4794.39 6394.39,4794.39 6435,4835 C65.2@6435,4895.63
$12N45711: LED7.1 U17.7 | length 806.3
  Top Layer w10: v1(4230,5290) 4230,5264.56 LED7.1@4239.56,5255 ; v1(4876.2,5115) U17.7@4876.2,5163.62
  Bottom Layer w10: v1(4230,5290) 4701.2,5290 v1(4876.2,5115)
$12N45712: LED7.2 U33.2 | length 114
  Top Layer w10: U33.2@4240.34,5170 4240.34,5184.91 LED7.2@4310.43,5255
$12N45719: LED5.1 R67.2 | length 54.7
  Top Layer w10: R67.2@6606.31,6133.17 6656.55,6133.17 LED5.1@6659.7,6130.02
$12N45720: LED6.1 R68.2 | length 54.7
  Top Layer w10: R68.2@6606.31,6063 6656.55,6063 LED6.1@6659.7,6066.15
$12N45721: D31.1 U2.21 | length 393.9
  Top Layer w15: U2.21@4452.6,5700 4476.42,5676.18 4509.37,5676.18 4555,5630.55 4555,5535 4484.22,5464.22 D31.1@4484.22,5397.11
$14N15222: U42.9 U46.10 | length 424
  Top Layer w10: U42.9@5907.31,3733.26 5930,3755.95 5930,4108.67 U46.10@5957.68,4136.35
$14N15270: CN2.2 E2.5 | length 1840.7
  Top Layer w10: E2.5@4147.87,3210 4147.87,3192.93 4175,3165.8 5585.8,3165.8 5840,3420 CN2.2@5840,3435
$14N15281: E2.7 U52.4 | length 2596.1
  Top Layer w10: E2.7@4147.87,3310 4207.47,3310 v1(4207.81,3309.67) ; v1(6615.01,3185.8) 6615.01,3207.8 6617.21,3210 U52.4@6617.21,3257.18
  Bottom Layer w10: v1(4207.81,3309.67) 4214.17,3316.03 4242.2,3288 4362.5,3288 4454.5,3196 6577.95,3196 6588.16,3185.8 v1(6615.01,3185.8)
$14N15285: E2.8 U52.5 | length 2652.9
  Top Layer w10: E2.8@4147.87,3360 4152.1,3355.77 4171.39,3355.77 4173.99,3358.37 4193.04,3358.37 4210.54,3340.87 v1(4210.54,3339.67) ; U52.5@6642.8,3257.18 6642.8,3210 6645.01,3207.8 v1(6645.01,3185.8)
  Bottom Layer w10: v1(4210.54,3339.67) 4215,3335.21 4215,3335 4248,3302 4368.3,3302 4460.3,3210 6634.94,3210 6645.01,3199.94 v1(6645.01,3185.8)
$14N15314: U52.12 U53.5 | length 129.4
  Top Layer w10: U52.12@6642.8,3482.82 U53.5@6642.8,3612.18
$14N15320: U52.13 U53.4 | length 129.4
  Top Layer w10: U52.13@6617.21,3482.82 U53.4@6617.21,3612.18
$14N15352: U53.12 U54.5 | length 124.4
  Top Layer w10: U53.12@6642.8,3837.82 U54.5@6642.8,3962.18
$14N15358: U53.13 U54.4 | length 124.4
  Top Layer w10: U53.13@6617.21,3837.82 U54.4@6617.21,3962.18
$14N15390: U54.12 U55.5 | length 134.4
  Top Layer w10: U54.12@6642.8,4187.82 U55.5@6642.8,4322.18
$14N15396: U54.13 U55.4 | length 134.4
  Top Layer w10: U54.13@6617.21,4187.82 U55.4@6617.21,4322.18
$14N18888: C101.2 R71.2 U58.7 | length 475.1
  Top Layer w10: U58.7@5298.98,4195.16 5295.8,4191.97 5292.15,4191.97 5291.57,4191.39 5282.55,4191.39 5273.22,4182.07 5273.22,4168.88 5308.1,4134 5469,4134 5511.92,4176.92 5531.65,4176.92 5569.75,4215.02 R71.2@5574.75,4215.02 5577.56,4212.22 C101.2@5577.56,4135
$14N18889: C101.1 U58.6 | length 363.8
  Top Layer w10: U58.6@5298.98,4214.84 5284.84,4214.84 5259.22,4189.22 5259.22,4163.08 5302.3,4120 5507.44,4120 C101.1@5522.44,4135
$14N18895: U58.5 U59.1 | length 198.6
  Top Layer w10: U58.5@5298.98,4234.53 5262,4271.52 5262,4349.53 5275.47,4363 5321.07,4363 U59.1@5323.66,4365.59
$14N18897: U42.1 U46.1 U59.4 | length 1551.2
  Top Layer w10: v1(5365,4310) 5401.93,4310 U59.4@5406.34,4314.41 ; v1(6250,4290) 6257.68,4297.68 U46.1@6257.68,4354.39 ; U42.1@6257.31,3951.3 6258.61,3950 v1(6290,3950)
  Bottom Layer w10: v1(5365,4310) 5725,3950 6210,3950 6250,3990 ; v1(6250,4290) 6250,3990 ; v1(6290,3950) 6250,3990
$14N20057: E2.1 R79.2 | length 395.5
  Top Layer w10: E2.1@3932.13,3360 3957.47,3360 4107.47,3510 4259.37,3510 R79.2@4263.72,3514.35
